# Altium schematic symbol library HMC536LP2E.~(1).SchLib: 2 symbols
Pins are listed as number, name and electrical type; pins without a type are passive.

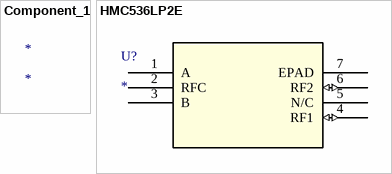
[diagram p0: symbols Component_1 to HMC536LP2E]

## Component_1
designator *

## HMC536LP2E
designator U?
No Description Available; Mfr_Name: Analog Devices Inc
footprint DFN_6_ADI
pins: 1 A, 2 RFC, 3 B, 4 RF1 (io), 5 N/C, 6 RF2 (io), 7 EPAD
